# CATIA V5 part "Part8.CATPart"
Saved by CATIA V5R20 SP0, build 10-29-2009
Part number: 3JT9.5X2X13.5
Revision: ANY
Definition: UNKNOWN
Nomenclature: 3JT9.5X2X13.5
Source: Unknown
Bounding box of the stored display mesh (mm): x -6.581 to 6.581, y -1 to 1, z -6.75 to 6.75
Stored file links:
  C:\Users\Utente\Desktop\IO LAVORO\3D X SITO CF\CUMSA\3D files PW\pw081230\pw081230_injection\Part8.CATPart
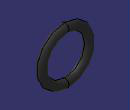
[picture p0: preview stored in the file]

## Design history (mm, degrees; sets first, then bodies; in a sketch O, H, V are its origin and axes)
Body1 "Revolución1" (main body)
  Solid1: solid without history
